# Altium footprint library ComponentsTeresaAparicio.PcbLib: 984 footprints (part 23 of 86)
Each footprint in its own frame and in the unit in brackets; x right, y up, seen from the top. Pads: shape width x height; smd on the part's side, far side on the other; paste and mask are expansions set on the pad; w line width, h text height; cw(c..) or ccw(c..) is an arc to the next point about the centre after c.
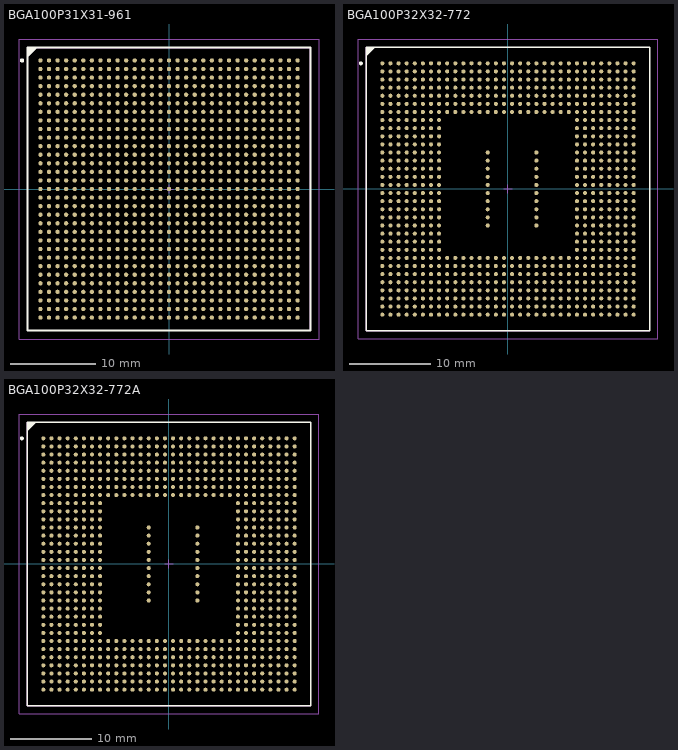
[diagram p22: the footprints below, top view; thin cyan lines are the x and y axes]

## BGA100P31X31-961 [mm] "BGA, 961-Leads, Body 33x33mm, Pitch 1mm"
height 3.5
pads (961):
  round 0.5 smd: A1(-15,15) A2(-14,15) A3(-13,15) A4(-12,15) A5(-11,15) A6(-10,15) A7(-9,15) A8(-8,15) A9(-7,15) A10(-6,15) A11(-5,15) A12(-4,15) A13(-3,15) A14(-2,15) A15(-1,15) A16(0,15) A17(1,15) A18(2,15) A19(3,15) A20(4,15) A21(5,15) A22(6,15) A23(7,15) A24(8,15) A25(9,15) A26(10,15) A27(11,15) A28(12,15) A29(13,15) A30(14,15) A31(15,15) AA1(-15,-5) AA2(-14,-5) AA3(-13,-5) AA4(-12,-5) AA5(-11,-5) AA6(-10,-5) AA7(-9,-5) AA8(-8,-5) AA9(-7,-5) AA10(-6,-5) AA11(-5,-5) AA12(-4,-5) AA13(-3,-5) AA14(-2,-5) AA15(-1,-5) AA16(0,-5) AA17(1,-5) AA18(2,-5) AA19(3,-5) AA20(4,-5) AA21(5,-5) AA22(6,-5) AA23(7,-5) AA24(8,-5) AA25(9,-5) AA26(10,-5) AA27(11,-5) AA28(12,-5) AA29(13,-5) AA30(14,-5) AA31(15,-5) AB1(-15,-6) AB2(-14,-6) AB3(-13,-6) AB4(-12,-6) AB5(-11,-6) AB6(-10,-6) AB7(-9,-6) AB8(-8,-6) AB9(-7,-6) AB10(-6,-6) AB11(-5,-6) AB12(-4,-6) AB13(-3,-6) AB14(-2,-6) AB15(-1,-6) AB16(0,-6) AB17(1,-6) AB18(2,-6) AB19(3,-6) AB20(4,-6) AB21(5,-6) AB22(6,-6) AB23(7,-6) AB24(8,-6) AB25(9,-6) AB26(10,-6) AB27(11,-6) AB28(12,-6) AB29(13,-6) AB30(14,-6) AB31(15,-6) AC1(-15,-7) AC2(-14,-7) AC3(-13,-7) AC4(-12,-7) AC5(-11,-7) AC6(-10,-7) AC7(-9,-7) AC8(-8,-7) AC9(-7,-7) AC10(-6,-7) AC11(-5,-7) AC12(-4,-7) AC13(-3,-7) AC14(-2,-7) AC15(-1,-7) AC16(0,-7) AC17(1,-7) AC18(2,-7) AC19(3,-7) AC20(4,-7) AC21(5,-7) AC22(6,-7) AC23(7,-7) AC24(8,-7) AC25(9,-7) AC26(10,-7) AC27(11,-7) AC28(12,-7) AC29(13,-7) AC30(14,-7) AC31(15,-7) AD1(-15,-8) AD2(-14,-8) AD3(-13,-8) AD4(-12,-8) AD5(-11,-8) AD6(-10,-8) AD7(-9,-8) AD8(-8,-8) AD9(-7,-8) AD10(-6,-8) AD11(-5,-8) AD12(-4,-8) AD13(-3,-8) AD14(-2,-8) AD15(-1,-8) AD16(0,-8) AD17(1,-8) AD18(2,-8) AD19(3,-8) AD20(4,-8) AD21(5,-8) AD22(6,-8) AD23(7,-8) AD24(8,-8) AD25(9,-8) AD26(10,-8) AD27(11,-8) AD28(12,-8) AD29(13,-8) AD30(14,-8) AD31(15,-8) AE1(-15,-9) AE2(-14,-9) AE3(-13,-9) AE4(-12,-9) AE5(-11,-9) AE6(-10,-9) AE7(-9,-9) AE8(-8,-9) AE9(-7,-9) AE10(-6,-9) AE11(-5,-9) AE12(-4,-9) AE13(-3,-9) AE14(-2,-9) AE15(-1,-9) AE16(0,-9) AE17(1,-9) AE18(2,-9) AE19(3,-9) AE20(4,-9) AE21(5,-9) AE22(6,-9) AE23(7,-9) AE24(8,-9) AE25(9,-9) AE26(10,-9) AE27(11,-9) AE28(12,-9) AE29(13,-9) AE30(14,-9) AE31(15,-9) AF1(-15,-10) AF2(-14,-10) AF3(-13,-10) AF4(-12,-10) AF5(-11,-10) AF6(-10,-10) AF7(-9,-10) AF8(-8,-10) AF9(-7,-10) AF10(-6,-10) AF11(-5,-10) AF12(-4,-10) AF13(-3,-10) AF14(-2,-10) AF15(-1,-10) AF16(0,-10) AF17(1,-10) AF18(2,-10) AF19(3,-10) AF20(4,-10) AF21(5,-10) AF22(6,-10) AF23(7,-10) AF24(8,-10) AF25(9,-10) AF26(10,-10) AF27(11,-10) AF28(12,-10) AF29(13,-10) AF30(14,-10) AF31(15,-10) AG1(-15,-11) AG2(-14,-11) AG3(-13,-11) AG4(-12,-11) AG5(-11,-11) AG6(-10,-11) AG7(-9,-11) AG8(-8,-11) AG9(-7,-11) AG10(-6,-11) AG11(-5,-11) AG12(-4,-11) AG13(-3,-11) AG14(-2,-11) AG15(-1,-11) AG16(0,-11) AG17(1,-11) AG18(2,-11) AG19(3,-11) AG20(4,-11) AG21(5,-11) AG22(6,-11) AG23(7,-11) AG24(8,-11) AG25(9,-11) AG26(10,-11) AG27(11,-11) AG28(12,-11) AG29(13,-11) AG30(14,-11) AG31(15,-11) AH1(-15,-12) AH2(-14,-12) AH3(-13,-12) AH4(-12,-12) AH5(-11,-12) AH6(-10,-12) AH7(-9,-12) AH8(-8,-12) AH9(-7,-12) AH10(-6,-12) AH11(-5,-12) AH12(-4,-12) AH13(-3,-12) AH14(-2,-12) AH15(-1,-12) AH16(0,-12) AH17(1,-12) AH18(2,-12) AH19(3,-12) AH20(4,-12) AH21(5,-12) AH22(6,-12) AH23(7,-12) AH24(8,-12) AH25(9,-12) AH26(10,-12) AH27(11,-12) AH28(12,-12) AH29(13,-12) AH30(14,-12) AH31(15,-12) AJ1(-15,-13) AJ2(-14,-13) AJ3(-13,-13) AJ4(-12,-13) AJ5(-11,-13) AJ6(-10,-13) AJ7(-9,-13) AJ8(-8,-13) AJ9(-7,-13) AJ10(-6,-13) AJ11(-5,-13) AJ12(-4,-13) AJ13(-3,-13) AJ14(-2,-13) AJ15(-1,-13) AJ16(0,-13) AJ17(1,-13) AJ18(2,-13) AJ19(3,-13) AJ20(4,-13) AJ21(5,-13) AJ22(6,-13) AJ23(7,-13) AJ24(8,-13) AJ25(9,-13) AJ26(10,-13) AJ27(11,-13) AJ28(12,-13) AJ29(13,-13) AJ30(14,-13) AJ31(15,-13) AK1(-15,-14) AK2(-14,-14) AK3(-13,-14) AK4(-12,-14) AK5(-11,-14) AK6(-10,-14) AK7(-9,-14) AK8(-8,-14) AK9(-7,-14) AK10(-6,-14) AK11(-5,-14) AK12(-4,-14) AK13(-3,-14) AK14(-2,-14) AK15(-1,-14) AK16(0,-14) AK17(1,-14) AK18(2,-14) AK19(3,-14) AK20(4,-14) AK21(5,-14) AK22(6,-14) AK23(7,-14) AK24(8,-14) AK25(9,-14) AK26(10,-14) AK27(11,-14) AK28(12,-14) AK29(13,-14) AK30(14,-14) AK31(15,-14) AL1(-15,-15) AL2(-14,-15) AL3(-13,-15) AL4(-12,-15) AL5(-11,-15) AL6(-10,-15) AL7(-9,-15) AL8(-8,-15) AL9(-7,-15) AL10(-6,-15) AL11(-5,-15) AL12(-4,-15) AL13(-3,-15) AL14(-2,-15) AL15(-1,-15) AL16(0,-15) AL17(1,-15) AL18(2,-15) AL19(3,-15) AL20(4,-15) AL21(5,-15) AL22(6,-15) AL23(7,-15) AL24(8,-15) AL25(9,-15) AL26(10,-15) AL27(11,-15) AL28(12,-15) AL29(13,-15) AL30(14,-15) AL31(15,-15) B1(-15,14) B2(-14,14) B3(-13,14) B4(-12,14) B5(-11,14) B6(-10,14) B7(-9,14) B8(-8,14) B9(-7,14) B10(-6,14) B11(-5,14) B12(-4,14) B13(-3,14) B14(-2,14) B15(-1,14) B16(0,14) B17(1,14) B18(2,14) B19(3,14) B20(4,14) B21(5,14) B22(6,14) B23(7,14) B24(8,14) B25(9,14) B26(10,14) B27(11,14) B28(12,14) B29(13,14) B30(14,14) B31(15,14) C1(-15,13) C2(-14,13) C3(-13,13) C4(-12,13) C5(-11,13) C6(-10,13) C7(-9,13) C8(-8,13) C9(-7,13) C10(-6,13) C11(-5,13) C12(-4,13) C13(-3,13) C14(-2,13) C15(-1,13) C16(0,13) C17(1,13) C18(2,13) C19(3,13) C20(4,13) C21(5,13) C22(6,13) C23(7,13) C24(8,13) C25(9,13) C26(10,13) C27(11,13) C28(12,13) C29(13,13) C30(14,13) C31(15,13) D1(-15,12) D2(-14,12) D3(-13,12) D4(-12,12) D5(-11,12) D6(-10,12) D7(-9,12) D8(-8,12) D9(-7,12) D10(-6,12) D11(-5,12) D12(-4,12) D13(-3,12) D14(-2,12) D15(-1,12) D16(0,12) D17(1,12) D18(2,12) D19(3,12) D20(4,12) D21(5,12) D22(6,12) D23(7,12) D24(8,12) D25(9,12) D26(10,12) D27(11,12) D28(12,12) D29(13,12) D30(14,12) D31(15,12) E1(-15,11) E2(-14,11) E3(-13,11) E4(-12,11) E5(-11,11) E6(-10,11) E7(-9,11) E8(-8,11) E9(-7,11) E10(-6,11) E11(-5,11) E12(-4,11) E13(-3,11) E14(-2,11) E15(-1,11) E16(0,11) E17(1,11) E18(2,11) E19(3,11) E20(4,11) E21(5,11) E22(6,11) E23(7,11) E24(8,11) E25(9,11) E26(10,11) E27(11,11) E28(12,11) E29(13,11) E30(14,11) E31(15,11) F1(-15,10) F2(-14,10) F3(-13,10) F4(-12,10) F5(-11,10) F6(-10,10) F7(-9,10) F8(-8,10) F9(-7,10) F10(-6,10) F11(-5,10) F12(-4,10) F13(-3,10) F14(-2,10) F15(-1,10) F16(0,10) F17(1,10) F18(2,10) F19(3,10) F20(4,10) F21(5,10) F22(6,10) F23(7,10) F24(8,10) F25(9,10) F26(10,10) F27(11,10) F28(12,10) F29(13,10) F30(14,10) F31(15,10) G1(-15,9) G2(-14,9) G3(-13,9) G4(-12,9) G5(-11,9) G6(-10,9) G7(-9,9) G8(-8,9) G9(-7,9) G10(-6,9) G11(-5,9) G12(-4,9) G13(-3,9) G14(-2,9) G15(-1,9) G16(0,9) G17(1,9) G18(2,9) G19(3,9) G20(4,9) G21(5,9) G22(6,9) G23(7,9) G24(8,9) G25(9,9) G26(10,9) G27(11,9) G28(12,9) G29(13,9) G30(14,9) G31(15,9) H1(-15,8) H2(-14,8) H3(-13,8) H4(-12,8) H5(-11,8) H6(-10,8) H7(-9,8) H8(-8,8) H9(-7,8) H10(-6,8) H11(-5,8) H12(-4,8) H13(-3,8) H14(-2,8) H15(-1,8) H16(0,8) H17(1,8) H18(2,8) H19(3,8) H20(4,8) H21(5,8) H22(6,8) H23(7,8) H24(8,8) H25(9,8) H26(10,8) H27(11,8) H28(12,8) H29(13,8) H30(14,8) H31(15,8) J1(-15,7) J2(-14,7) J3(-13,7) J4(-12,7) J5(-11,7) J6(-10,7) J7(-9,7) J8(-8,7) J9(-7,7) J10(-6,7) J11(-5,7) J12(-4,7) J13(-3,7) J14(-2,7) J15(-1,7) J16(0,7) J17(1,7) J18(2,7) J19(3,7) J20(4,7) J21(5,7) J22(6,7) J23(7,7) J24(8,7) J25(9,7) J26(10,7) J27(11,7) J28(12,7) J29(13,7) J30(14,7) J31(15,7) K1(-15,6) K2(-14,6) K3(-13,6) K4(-12,6) K5(-11,6) K6(-10,6) K7(-9,6) K8(-8,6) K9(-7,6) K10(-6,6) K11(-5,6) K12(-4,6) K13(-3,6) K14(-2,6) K15(-1,6) K16(0,6) K17(1,6) K18(2,6) K19(3,6) K20(4,6) K21(5,6) K22(6,6) K23(7,6) K24(8,6) K25(9,6) K26(10,6) K27(11,6) K28(12,6) K29(13,6) K30(14,6) K31(15,6) L1(-15,5) L2(-14,5) L3(-13,5) L4(-12,5) L5(-11,5) L6(-10,5) L7(-9,5) L8(-8,5) L9(-7,5) L10(-6,5) L11(-5,5) L12(-4,5) L13(-3,5) L14(-2,5) L15(-1,5) L16(0,5) L17(1,5) L18(2,5) L19(3,5) L20(4,5) L21(5,5) L22(6,5) L23(7,5) L24(8,5) L25(9,5) L26(10,5) L27(11,5) L28(12,5) L29(13,5) L30(14,5) L31(15,5) M1(-15,4) M2(-14,4) M3(-13,4) M4(-12,4) M5(-11,4) M6(-10,4) M7(-9,4) M8(-8,4) M9(-7,4) M10(-6,4) M11(-5,4) M12(-4,4) M13(-3,4) M14(-2,4) M15(-1,4) M16(0,4) M17(1,4) M18(2,4) M19(3,4) M20(4,4) M21(5,4) M22(6,4) M23(7,4) M24(8,4) M25(9,4) M26(10,4) M27(11,4) M28(12,4) M29(13,4) M30(14,4) M31(15,4) N1(-15,3) N2(-14,3) N3(-13,3) N4(-12,3) N5(-11,3) N6(-10,3) N7(-9,3) N8(-8,3) N9(-7,3) N10(-6,3) N11(-5,3) N12(-4,3) N13(-3,3) N14(-2,3) N15(-1,3) N16(0,3) N17(1,3) N18(2,3) N19(3,3) N20(4,3) N21(5,3) N22(6,3) N23(7,3) N24(8,3) N25(9,3) N26(10,3) N27(11,3) N28(12,3) N29(13,3) N30(14,3) N31(15,3) P1(-15,2) P2(-14,2) P3(-13,2) P4(-12,2) P5(-11,2) P6(-10,2) P7(-9,2) P8(-8,2) P9(-7,2) P10(-6,2) P11(-5,2) P12(-4,2) P13(-3,2) P14(-2,2) P15(-1,2) P16(0,2) P17(1,2) P18(2,2) P19(3,2) P20(4,2) P21(5,2) P22(6,2) P23(7,2) P24(8,2) P25(9,2) P26(10,2) P27(11,2) P28(12,2) P29(13,2) P30(14,2) P31(15,2) R1(-15,1) R2(-14,1) R3(-13,1) R4(-12,1) R5(-11,1) R6(-10,1) R7(-9,1) R8(-8,1) R9(-7,1) R10(-6,1) R11(-5,1) R12(-4,1) R13(-3,1) R14(-2,1) R15(-1,1) R16(0,1) R17(1,1) R18(2,1) R19(3,1) R20(4,1) R21(5,1) R22(6,1) R23(7,1) R24(8,1) R25(9,1) R26(10,1) R27(11,1) R28(12,1) R29(13,1) R30(14,1) R31(15,1) T1(-15,0) T2(-14,0) T3(-13,0) T4(-12,0) T5(-11,0) T6(-10,0) T7(-9,0) T8(-8,0) T9(-7,0) T10(-6,0) T11(-5,0) T12(-4,0) T13(-3,0) T14(-2,0) T15(-1,0) T16(0,0) T17(1,0) T18(2,0) T19(3,0) T20(4,0) T21(5,0) T22(6,0) T23(7,0) T24(8,0) T25(9,0) T26(10,0) T27(11,0) T28(12,0) T29(13,0) T30(14,0) T31(15,0) U1(-15,-1) U2(-14,-1) U3(-13,-1) U4(-12,-1) U5(-11,-1) U6(-10,-1) U7(-9,-1) U8(-8,-1) U9(-7,-1) U10(-6,-1) U11(-5,-1) U12(-4,-1) U13(-3,-1) U14(-2,-1) U15(-1,-1) U16(0,-1) U17(1,-1) U18(2,-1) U19(3,-1) U20(4,-1) U21(5,-1) U22(6,-1) U23(7,-1) U24(8,-1) U25(9,-1) U26(10,-1) U27(11,-1) U28(12,-1) U29(13,-1) U30(14,-1) U31(15,-1) V1(-15,-2) V2(-14,-2) V3(-13,-2) V4(-12,-2) V5(-11,-2) V6(-10,-2) V7(-9,-2) V8(-8,-2) V9(-7,-2) V10(-6,-2) V11(-5,-2) V12(-4,-2) V13(-3,-2) V14(-2,-2) V15(-1,-2) V16(0,-2) V17(1,-2) V18(2,-2) V19(3,-2) V20(4,-2) V21(5,-2) V22(6,-2) V23(7,-2) V24(8,-2) V25(9,-2) V26(10,-2) V27(11,-2) V28(12,-2) V29(13,-2) V30(14,-2) V31(15,-2) W1(-15,-3) W2(-14,-3) W3(-13,-3) W4(-12,-3) W5(-11,-3) W6(-10,-3) W7(-9,-3) W8(-8,-3) W9(-7,-3) W10(-6,-3) W11(-5,-3) W12(-4,-3) W13(-3,-3) W14(-2,-3) W15(-1,-3) W16(0,-3) W17(1,-3) W18(2,-3) W19(3,-3) W20(4,-3) W21(5,-3) W22(6,-3) W23(7,-3) W24(8,-3) W25(9,-3) W26(10,-3) W27(11,-3) W28(12,-3) W29(13,-3) W30(14,-3) W31(15,-3) Y1(-15,-4) Y2(-14,-4) Y3(-13,-4) Y4(-12,-4) Y5(-11,-4) Y6(-10,-4) Y7(-9,-4) Y8(-8,-4) Y9(-7,-4) Y10(-6,-4) Y11(-5,-4) Y12(-4,-4) Y13(-3,-4) Y14(-2,-4) Y15(-1,-4) Y16(0,-4) Y17(1,-4) Y18(2,-4) Y19(3,-4) Y20(4,-4) Y21(5,-4) Y22(6,-4) Y23(7,-4) Y24(8,-4) Y25(9,-4) Y26(10,-4) Y27(11,-4) Y28(12,-4) Y29(13,-4) Y30(14,-4) Y31(15,-4)
Top Overlay:
  circle w0.25: c-17.15,15 r0.125
  region: -15.5,16.5 -16.5,15.5 -16.5,16.5
  lines w0.2: -16.5,15.5 -15.5,16.5 ; -16.5,-16.5 -16.5,16.5 16.5,16.5 16.5,-16.5 -16.5,-16.5
Mechanical 13:
  lines w0.1: -16.5,-16.5 -16.5,16.5 16.5,16.5 16.5,-16.5 -16.5,-16.5
Mechanical 15:
  lines w0.1: -0.5,0 0.5,0 ; 0,-0.5 0,0.5 ; -17.5,-17.5 -17.5,17.5 17.5,17.5 17.5,-17.5 -17.5,-17.5
3D body: height 0, standoff 0, extent -16.5,-16.5 16.5,16.5

## BGA100P32X32-772 [mm] "772-Ball Ball Grid Array 1 mm Pitch"
height 3.6
pads (772):
  round 0.5 smd: A1(-15.5,15.5) A2(-14.5,15.5) A3(-13.5,15.5) A4(-12.5,15.5) A5(-11.5,15.5) A6(-10.5,15.5) A7(-9.5,15.5) A8(-8.5,15.5) A9(-7.5,15.5) A10(-6.5,15.5) A11(-5.5,15.5) A12(-4.5,15.5) A13(-3.5,15.5) A14(-2.5,15.5) A15(-1.5,15.5) A16(-0.5,15.5) A17(0.5,15.5) A18(1.5,15.5) A19(2.5,15.5) A20(3.5,15.5) A21(4.5,15.5) A22(5.5,15.5) A23(6.5,15.5) A24(7.5,15.5) A25(8.5,15.5) A26(9.5,15.5) A27(10.5,15.5) A28(11.5,15.5) A29(12.5,15.5) A30(13.5,15.5) A31(14.5,15.5) A32(15.5,15.5) AA1(-15.5,-4.5) AA2(-14.5,-4.5) AA3(-13.5,-4.5) AA4(-12.5,-4.5) AA5(-11.5,-4.5) AA6(-10.5,-4.5) AA7(-9.5,-4.5) AA8(-8.5,-4.5) AA14(-2.5,-4.5) AA20(3.5,-4.5) AA25(8.5,-4.5) AA26(9.5,-4.5) AA27(10.5,-4.5) AA28(11.5,-4.5) AA29(12.5,-4.5) AA30(13.5,-4.5) AA31(14.5,-4.5) AA32(15.5,-4.5) AB1(-15.5,-5.5) AB2(-14.5,-5.5) AB3(-13.5,-5.5) AB4(-12.5,-5.5) AB5(-11.5,-5.5) AB6(-10.5,-5.5) AB7(-9.5,-5.5) AB8(-8.5,-5.5) AB25(8.5,-5.5) AB26(9.5,-5.5) AB27(10.5,-5.5) AB28(11.5,-5.5) AB29(12.5,-5.5) AB30(13.5,-5.5) AB31(14.5,-5.5) AB32(15.5,-5.5) AC1(-15.5,-6.5) AC2(-14.5,-6.5) AC3(-13.5,-6.5) AC4(-12.5,-6.5) AC5(-11.5,-6.5) AC6(-10.5,-6.5) AC7(-9.5,-6.5) AC8(-8.5,-6.5) AC25(8.5,-6.5) AC26(9.5,-6.5) AC27(10.5,-6.5) AC28(11.5,-6.5) AC29(12.5,-6.5) AC30(13.5,-6.5) AC31(14.5,-6.5) AC32(15.5,-6.5) AD1(-15.5,-7.5) AD2(-14.5,-7.5) AD3(-13.5,-7.5) AD4(-12.5,-7.5) AD5(-11.5,-7.5) AD6(-10.5,-7.5) AD7(-9.5,-7.5) AD8(-8.5,-7.5) AD25(8.5,-7.5) AD26(9.5,-7.5) AD27(10.5,-7.5) AD28(11.5,-7.5) AD29(12.5,-7.5) AD30(13.5,-7.5) AD31(14.5,-7.5) AD32(15.5,-7.5) AE1(-15.5,-8.5) AE2(-14.5,-8.5) AE3(-13.5,-8.5) AE4(-12.5,-8.5) AE5(-11.5,-8.5) AE6(-10.5,-8.5) AE7(-9.5,-8.5) AE8(-8.5,-8.5) AE9(-7.5,-8.5) AE10(-6.5,-8.5) AE11(-5.5,-8.5) AE12(-4.5,-8.5) AE13(-3.5,-8.5) AE14(-2.5,-8.5) AE15(-1.5,-8.5) AE16(-0.5,-8.5) AE17(0.5,-8.5) AE18(1.5,-8.5) AE19(2.5,-8.5) AE20(3.5,-8.5) AE21(4.5,-8.5) AE22(5.5,-8.5) AE23(6.5,-8.5) AE24(7.5,-8.5) AE25(8.5,-8.5) AE26(9.5,-8.5) AE27(10.5,-8.5) AE28(11.5,-8.5) AE29(12.5,-8.5) AE30(13.5,-8.5) AE31(14.5,-8.5) AE32(15.5,-8.5) AF1(-15.5,-9.5) AF2(-14.5,-9.5) AF3(-13.5,-9.5) AF4(-12.5,-9.5) AF5(-11.5,-9.5) AF6(-10.5,-9.5) AF7(-9.5,-9.5) AF8(-8.5,-9.5) AF9(-7.5,-9.5) AF10(-6.5,-9.5) AF11(-5.5,-9.5) AF12(-4.5,-9.5) AF13(-3.5,-9.5) AF14(-2.5,-9.5) AF15(-1.5,-9.5) AF16(-0.5,-9.5) AF17(0.5,-9.5) AF18(1.5,-9.5) AF19(2.5,-9.5) AF20(3.5,-9.5) AF21(4.5,-9.5) AF22(5.5,-9.5) AF23(6.5,-9.5) AF24(7.5,-9.5) AF25(8.5,-9.5) AF26(9.5,-9.5) AF27(10.5,-9.5) AF28(11.5,-9.5) AF29(12.5,-9.5) AF30(13.5,-9.5) AF31(14.5,-9.5) AF32(15.5,-9.5) AG1(-15.5,-10.5) AG2(-14.5,-10.5) AG3(-13.5,-10.5) AG4(-12.5,-10.5) AG5(-11.5,-10.5) AG6(-10.5,-10.5) AG7(-9.5,-10.5) AG8(-8.5,-10.5) AG9(-7.5,-10.5) AG10(-6.5,-10.5) AG11(-5.5,-10.5) AG12(-4.5,-10.5) AG13(-3.5,-10.5) AG14(-2.5,-10.5) AG15(-1.5,-10.5) AG16(-0.5,-10.5) AG17(0.5,-10.5) AG18(1.5,-10.5) AG19(2.5,-10.5) AG20(3.5,-10.5) AG21(4.5,-10.5) AG22(5.5,-10.5) AG23(6.5,-10.5) AG24(7.5,-10.5) AG25(8.5,-10.5) AG26(9.5,-10.5) AG27(10.5,-10.5) AG28(11.5,-10.5) AG29(12.5,-10.5) AG30(13.5,-10.5) AG31(14.5,-10.5) AG32(15.5,-10.5) AH1(-15.5,-11.5) AH2(-14.5,-11.5) AH3(-13.5,-11.5) AH4(-12.5,-11.5) AH5(-11.5,-11.5) AH6(-10.5,-11.5) AH7(-9.5,-11.5) AH8(-8.5,-11.5) AH9(-7.5,-11.5) AH10(-6.5,-11.5) AH11(-5.5,-11.5) AH12(-4.5,-11.5) AH13(-3.5,-11.5) AH14(-2.5,-11.5) AH15(-1.5,-11.5) AH16(-0.5,-11.5) AH17(0.5,-11.5) AH18(1.5,-11.5) AH19(2.5,-11.5) AH20(3.5,-11.5) AH21(4.5,-11.5) AH22(5.5,-11.5) AH23(6.5,-11.5) AH24(7.5,-11.5) AH25(8.5,-11.5) AH26(9.5,-11.5) AH27(10.5,-11.5) AH28(11.5,-11.5) AH29(12.5,-11.5) AH30(13.5,-11.5) AH31(14.5,-11.5) AH32(15.5,-11.5) AJ1(-15.5,-12.5) AJ2(-14.5,-12.5) AJ3(-13.5,-12.5) AJ4(-12.5,-12.5) AJ5(-11.5,-12.5) AJ6(-10.5,-12.5) AJ7(-9.5,-12.5) AJ8(-8.5,-12.5) AJ9(-7.5,-12.5) AJ10(-6.5,-12.5) AJ11(-5.5,-12.5) AJ12(-4.5,-12.5) AJ13(-3.5,-12.5) AJ14(-2.5,-12.5) AJ15(-1.5,-12.5) AJ16(-0.5,-12.5) AJ17(0.5,-12.5) AJ18(1.5,-12.5) AJ19(2.5,-12.5) AJ20(3.5,-12.5) AJ21(4.5,-12.5) AJ22(5.5,-12.5) AJ23(6.5,-12.5) AJ24(7.5,-12.5) AJ25(8.5,-12.5) AJ26(9.5,-12.5) AJ27(10.5,-12.5) AJ28(11.5,-12.5) AJ29(12.5,-12.5) AJ30(13.5,-12.5) AJ31(14.5,-12.5) AJ32(15.5,-12.5) AK1(-15.5,-13.5) AK2(-14.5,-13.5) AK3(-13.5,-13.5) AK4(-12.5,-13.5) AK5(-11.5,-13.5) AK6(-10.5,-13.5) AK7(-9.5,-13.5) AK8(-8.5,-13.5) AK9(-7.5,-13.5) AK10(-6.5,-13.5) AK11(-5.5,-13.5) AK12(-4.5,-13.5) AK13(-3.5,-13.5) AK14(-2.5,-13.5) AK15(-1.5,-13.5) AK16(-0.5,-13.5) AK17(0.5,-13.5) AK18(1.5,-13.5) AK19(2.5,-13.5) AK20(3.5,-13.5) AK21(4.5,-13.5) AK22(5.5,-13.5) AK23(6.5,-13.5) AK24(7.5,-13.5) AK25(8.5,-13.5) AK26(9.5,-13.5) AK27(10.5,-13.5) AK28(11.5,-13.5) AK29(12.5,-13.5) AK30(13.5,-13.5) AK31(14.5,-13.5) AK32(15.5,-13.5) AL1(-15.5,-14.5) AL2(-14.5,-14.5) AL3(-13.5,-14.5) AL4(-12.5,-14.5) AL5(-11.5,-14.5) AL6(-10.5,-14.5) AL7(-9.5,-14.5) AL8(-8.5,-14.5) AL9(-7.5,-14.5) AL10(-6.5,-14.5) AL11(-5.5,-14.5) AL12(-4.5,-14.5) AL13(-3.5,-14.5) AL14(-2.5,-14.5) AL15(-1.5,-14.5) AL16(-0.5,-14.5) AL17(0.5,-14.5) AL18(1.5,-14.5) AL19(2.5,-14.5) AL20(3.5,-14.5) AL21(4.5,-14.5) AL22(5.5,-14.5) AL23(6.5,-14.5) AL24(7.5,-14.5) AL25(8.5,-14.5) AL26(9.5,-14.5) AL27(10.5,-14.5) AL28(11.5,-14.5) AL29(12.5,-14.5) AL30(13.5,-14.5) AL31(14.5,-14.5) AL32(15.5,-14.5) AM1(-15.5,-15.5) AM2(-14.5,-15.5) AM3(-13.5,-15.5) AM4(-12.5,-15.5) AM5(-11.5,-15.5) AM6(-10.5,-15.5) AM7(-9.5,-15.5) AM8(-8.5,-15.5) AM9(-7.5,-15.5) AM10(-6.5,-15.5) AM11(-5.5,-15.5) AM12(-4.5,-15.5) AM13(-3.5,-15.5) AM14(-2.5,-15.5) AM15(-1.5,-15.5) AM16(-0.5,-15.5) AM17(0.5,-15.5) AM18(1.5,-15.5) AM19(2.5,-15.5) AM20(3.5,-15.5) AM21(4.5,-15.5) AM22(5.5,-15.5) AM23(6.5,-15.5) AM24(7.5,-15.5) AM25(8.5,-15.5) AM26(9.5,-15.5) AM27(10.5,-15.5) AM28(11.5,-15.5) AM29(12.5,-15.5) AM30(13.5,-15.5) AM31(14.5,-15.5) AM32(15.5,-15.5) B1(-15.5,14.5) B2(-14.5,14.5) B3(-13.5,14.5) B4(-12.5,14.5) B5(-11.5,14.5) B6(-10.5,14.5) B7(-9.5,14.5) B8(-8.5,14.5) B9(-7.5,14.5) B10(-6.5,14.5) B11(-5.5,14.5) B12(-4.5,14.5) B13(-3.5,14.5) B14(-2.5,14.5) B15(-1.5,14.5) B16(-0.5,14.5) B17(0.5,14.5) B18(1.5,14.5) B19(2.5,14.5) B20(3.5,14.5) B21(4.5,14.5) B22(5.5,14.5) B23(6.5,14.5) B24(7.5,14.5) B25(8.5,14.5) B26(9.5,14.5) B27(10.5,14.5) B28(11.5,14.5) B29(12.5,14.5) B30(13.5,14.5) B31(14.5,14.5) B32(15.5,14.5) C1(-15.5,13.5) C2(-14.5,13.5) C3(-13.5,13.5) C4(-12.5,13.5) C5(-11.5,13.5) C6(-10.5,13.5) C7(-9.5,13.5) C8(-8.5,13.5) C9(-7.5,13.5) C10(-6.5,13.5) C11(-5.5,13.5) C12(-4.5,13.5) C13(-3.5,13.5) C14(-2.5,13.5) C15(-1.5,13.5) C16(-0.5,13.5) C17(0.5,13.5) C18(1.5,13.5) C19(2.5,13.5) C20(3.5,13.5) C21(4.5,13.5) C22(5.5,13.5) C23(6.5,13.5) C24(7.5,13.5) C25(8.5,13.5) C26(9.5,13.5) C27(10.5,13.5) C28(11.5,13.5) C29(12.5,13.5) C30(13.5,13.5) C31(14.5,13.5) C32(15.5,13.5) D1(-15.5,12.5) D2(-14.5,12.5) D3(-13.5,12.5) D4(-12.5,12.5) D5(-11.5,12.5) D6(-10.5,12.5) D7(-9.5,12.5) D8(-8.5,12.5) D9(-7.5,12.5) D10(-6.5,12.5) D11(-5.5,12.5) D12(-4.5,12.5) D13(-3.5,12.5) D14(-2.5,12.5) D15(-1.5,12.5) D16(-0.5,12.5) D17(0.5,12.5) D18(1.5,12.5) D19(2.5,12.5) D20(3.5,12.5) D21(4.5,12.5) D22(5.5,12.5) D23(6.5,12.5) D24(7.5,12.5) D25(8.5,12.5) D26(9.5,12.5) D27(10.5,12.5) D28(11.5,12.5) D29(12.5,12.5) D30(13.5,12.5) D31(14.5,12.5) D32(15.5,12.5) E1(-15.5,11.5) E2(-14.5,11.5) E3(-13.5,11.5) E4(-12.5,11.5) E5(-11.5,11.5) E6(-10.5,11.5) E7(-9.5,11.5) E8(-8.5,11.5) E9(-7.5,11.5) E10(-6.5,11.5) E11(-5.5,11.5) E12(-4.5,11.5) E13(-3.5,11.5) E14(-2.5,11.5) E15(-1.5,11.5) E16(-0.5,11.5) E17(0.5,11.5) E18(1.5,11.5) E19(2.5,11.5) E20(3.5,11.5) E21(4.5,11.5) E22(5.5,11.5) E23(6.5,11.5) E24(7.5,11.5) E25(8.5,11.5) E26(9.5,11.5) E27(10.5,11.5) E28(11.5,11.5) E29(12.5,11.5) E30(13.5,11.5) E31(14.5,11.5) E32(15.5,11.5) F1(-15.5,10.5) F2(-14.5,10.5) F3(-13.5,10.5) F4(-12.5,10.5) F5(-11.5,10.5) F6(-10.5,10.5) F7(-9.5,10.5) F8(-8.5,10.5) F9(-7.5,10.5) F10(-6.5,10.5) F11(-5.5,10.5) F12(-4.5,10.5) F13(-3.5,10.5) F14(-2.5,10.5) F15(-1.5,10.5) F16(-0.5,10.5) F17(0.5,10.5) F18(1.5,10.5) F19(2.5,10.5) F20(3.5,10.5) F21(4.5,10.5) F22(5.5,10.5) F23(6.5,10.5) F24(7.5,10.5) F25(8.5,10.5) F26(9.5,10.5) F27(10.5,10.5) F28(11.5,10.5) F29(12.5,10.5) F30(13.5,10.5) F31(14.5,10.5) F32(15.5,10.5) G1(-15.5,9.5) G2(-14.5,9.5) G3(-13.5,9.5) G4(-12.5,9.5) G5(-11.5,9.5) G6(-10.5,9.5) G7(-9.5,9.5) G8(-8.5,9.5) G9(-7.5,9.5) G10(-6.5,9.5) G11(-5.5,9.5) G12(-4.5,9.5) G13(-3.5,9.5) G14(-2.5,9.5) G15(-1.5,9.5) G16(-0.5,9.5) G17(0.5,9.5) G18(1.5,9.5) G19(2.5,9.5) G20(3.5,9.5) G21(4.5,9.5) G22(5.5,9.5) G23(6.5,9.5) G24(7.5,9.5) G25(8.5,9.5) G26(9.5,9.5) G27(10.5,9.5) G28(11.5,9.5) G29(12.5,9.5) G30(13.5,9.5) G31(14.5,9.5) G32(15.5,9.5) H1(-15.5,8.5) H2(-14.5,8.5) H3(-13.5,8.5) H4(-12.5,8.5) H5(-11.5,8.5) H6(-10.5,8.5) H7(-9.5,8.5) H8(-8.5,8.5) H25(8.5,8.5) H26(9.5,8.5) H27(10.5,8.5) H28(11.5,8.5) H29(12.5,8.5) H30(13.5,8.5) H31(14.5,8.5) H32(15.5,8.5) J1(-15.5,7.5) J2(-14.5,7.5) J3(-13.5,7.5) J4(-12.5,7.5) J5(-11.5,7.5) J6(-10.5,7.5) J7(-9.5,7.5) J8(-8.5,7.5) J25(8.5,7.5) J26(9.5,7.5) J27(10.5,7.5) J28(11.5,7.5) J29(12.5,7.5) J30(13.5,7.5) J31(14.5,7.5) J32(15.5,7.5) K1(-15.5,6.5) K2(-14.5,6.5) K3(-13.5,6.5) K4(-12.5,6.5) K5(-11.5,6.5) K6(-10.5,6.5) K7(-9.5,6.5) K8(-8.5,6.5) K25(8.5,6.5) K26(9.5,6.5) K27(10.5,6.5) K28(11.5,6.5) K29(12.5,6.5) K30(13.5,6.5) K31(14.5,6.5) K32(15.5,6.5) L1(-15.5,5.5) L2(-14.5,5.5) L3(-13.5,5.5) L4(-12.5,5.5) L5(-11.5,5.5) L6(-10.5,5.5) L7(-9.5,5.5) L8(-8.5,5.5) L25(8.5,5.5) L26(9.5,5.5) L27(10.5,5.5) L28(11.5,5.5) L29(12.5,5.5) L30(13.5,5.5) L31(14.5,5.5) L32(15.5,5.5) M1(-15.5,4.5) M2(-14.5,4.5) M3(-13.5,4.5) M4(-12.5,4.5) M5(-11.5,4.5) M6(-10.5,4.5) M7(-9.5,4.5) M8(-8.5,4.5) M14(-2.5,4.5) M20(3.5,4.5) M25(8.5,4.5) M26(9.5,4.5) M27(10.5,4.5) M28(11.5,4.5) M29(12.5,4.5) M30(13.5,4.5) M31(14.5,4.5) M32(15.5,4.5) N1(-15.5,3.5) N2(-14.5,3.5) N3(-13.5,3.5) N4(-12.5,3.5) N5(-11.5,3.5) N6(-10.5,3.5) N7(-9.5,3.5) N8(-8.5,3.5) N14(-2.5,3.5) N20(3.5,3.5) N25(8.5,3.5) N26(9.5,3.5) N27(10.5,3.5) N28(11.5,3.5) N29(12.5,3.5) N30(13.5,3.5) N31(14.5,3.5) N32(15.5,3.5) P1(-15.5,2.5) P2(-14.5,2.5) P3(-13.5,2.5) P4(-12.5,2.5) P5(-11.5,2.5) P6(-10.5,2.5) P7(-9.5,2.5) P8(-8.5,2.5) P14(-2.5,2.5) P20(3.5,2.5) P25(8.5,2.5) P26(9.5,2.5) P27(10.5,2.5) P28(11.5,2.5) P29(12.5,2.5) P30(13.5,2.5) P31(14.5,2.5) P32(15.5,2.5) R1(-15.5,1.5) R2(-14.5,1.5) R3(-13.5,1.5) R4(-12.5,1.5) R5(-11.5,1.5) R6(-10.5,1.5) R7(-9.5,1.5) R8(-8.5,1.5) R14(-2.5,1.5) R20(3.5,1.5) R25(8.5,1.5) R26(9.5,1.5) R27(10.5,1.5) R28(11.5,1.5) R29(12.5,1.5) R30(13.5,1.5) R31(14.5,1.5) R32(15.5,1.5) T1(-15.5,0.5) T2(-14.5,0.5) T3(-13.5,0.5) T4(-12.5,0.5) T5(-11.5,0.5) T6(-10.5,0.5) T7(-9.5,0.5) T8(-8.5,0.5) T14(-2.5,0.5) T20(3.5,0.5) T25(8.5,0.5) T26(9.5,0.5) T27(10.5,0.5) T28(11.5,0.5) T29(12.5,0.5) T30(13.5,0.5) T31(14.5,0.5) T32(15.5,0.5) U1(-15.5,-0.5) U2(-14.5,-0.5) U3(-13.5,-0.5) U4(-12.5,-0.5) U5(-11.5,-0.5) U6(-10.5,-0.5) U7(-9.5,-0.5) U8(-8.5,-0.5) U14(-2.5,-0.5) U20(3.5,-0.5) U25(8.5,-0.5) U26(9.5,-0.5) U27(10.5,-0.5) U28(11.5,-0.5) U29(12.5,-0.5) U30(13.5,-0.5) U31(14.5,-0.5) U32(15.5,-0.5) V1(-15.5,-1.5) V2(-14.5,-1.5) V3(-13.5,-1.5) V4(-12.5,-1.5) V5(-11.5,-1.5) V6(-10.5,-1.5) V7(-9.5,-1.5) V8(-8.5,-1.5) V14(-2.5,-1.5) V20(3.5,-1.5) V25(8.5,-1.5) V26(9.5,-1.5) V27(10.5,-1.5) V28(11.5,-1.5) V29(12.5,-1.5) V30(13.5,-1.5) V31(14.5,-1.5) V32(15.5,-1.5) W1(-15.5,-2.5) W2(-14.5,-2.5) W3(-13.5,-2.5) W4(-12.5,-2.5) W5(-11.5,-2.5) W6(-10.5,-2.5) W7(-9.5,-2.5) W8(-8.5,-2.5) W14(-2.5,-2.5) W20(3.5,-2.5) W25(8.5,-2.5) W26(9.5,-2.5) W27(10.5,-2.5) W28(11.5,-2.5) W29(12.5,-2.5) W30(13.5,-2.5) W31(14.5,-2.5) W32(15.5,-2.5) Y1(-15.5,-3.5) Y2(-14.5,-3.5) Y3(-13.5,-3.5) Y4(-12.5,-3.5) Y5(-11.5,-3.5) Y6(-10.5,-3.5) Y7(-9.5,-3.5) Y8(-8.5,-3.5) Y14(-2.5,-3.5) Y20(3.5,-3.5) Y25(8.5,-3.5) Y26(9.5,-3.5) Y27(10.5,-3.5) Y28(11.5,-3.5) Y29(12.5,-3.5) Y30(13.5,-3.5) Y31(14.5,-3.5) Y32(15.5,-3.5)
Top Overlay:
  circle w0.25: c-18.15,15.5 r0.125
  region: -16.5,17.5 -17.5,16.5 -17.5,17.5
  lines w0.2: -17.5,16.5 -16.5,17.5 ; -17.5,-17.5 17.5,-17.5 17.5,17.5 -17.5,17.5 -17.5,-17.5
Mechanical 13:
  lines w0.1: -17.5,-17.5 17.5,-17.5 17.5,17.5 -17.5,17.5 -17.5,-17.5
Mechanical 15:
  lines w0.1: -0.5,0 0.5,0 ; 0,-0.5 0,0.5 ; -18.5,-18.5 18.5,-18.5 18.5,18.5 -18.5,18.5 -18.5,-18.5
3D body: height 0, standoff 0, extent -17.5,-17.5 17.5,17.5

## BGA100P32X32-772A [mm] "772-Ball Ball Grid Array 1 mm Pitch"
height 3.48
pads (772):
  round 0.5 smd: A1(-15.5,15.5) A2(-14.5,15.5) A3(-13.5,15.5) A4(-12.5,15.5) A5(-11.5,15.5) A6(-10.5,15.5) A7(-9.5,15.5) A8(-8.5,15.5) A9(-7.5,15.5) A10(-6.5,15.5) A11(-5.5,15.5) A12(-4.5,15.5) A13(-3.5,15.5) A14(-2.5,15.5) A15(-1.5,15.5) A16(-0.5,15.5) A17(0.5,15.5) A18(1.5,15.5) A19(2.5,15.5) A20(3.5,15.5) A21(4.5,15.5) A22(5.5,15.5) A23(6.5,15.5) A24(7.5,15.5) A25(8.5,15.5) A26(9.5,15.5) A27(10.5,15.5) A28(11.5,15.5) A29(12.5,15.5) A30(13.5,15.5) A31(14.5,15.5) A32(15.5,15.5) AA1(-15.5,-4.5) AA2(-14.5,-4.5) AA3(-13.5,-4.5) AA4(-12.5,-4.5) AA5(-11.5,-4.5) AA6(-10.5,-4.5) AA7(-9.5,-4.5) AA8(-8.5,-4.5) AA14(-2.5,-4.5) AA20(3.5,-4.5) AA25(8.5,-4.5) AA26(9.5,-4.5) AA27(10.5,-4.5) AA28(11.5,-4.5) AA29(12.5,-4.5) AA30(13.5,-4.5) AA31(14.5,-4.5) AA32(15.5,-4.5) AB1(-15.5,-5.5) AB2(-14.5,-5.5) AB3(-13.5,-5.5) AB4(-12.5,-5.5) AB5(-11.5,-5.5) AB6(-10.5,-5.5) AB7(-9.5,-5.5) AB8(-8.5,-5.5) AB25(8.5,-5.5) AB26(9.5,-5.5) AB27(10.5,-5.5) AB28(11.5,-5.5) AB29(12.5,-5.5) AB30(13.5,-5.5) AB31(14.5,-5.5) AB32(15.5,-5.5) AC1(-15.5,-6.5) AC2(-14.5,-6.5) AC3(-13.5,-6.5) AC4(-12.5,-6.5) AC5(-11.5,-6.5) AC6(-10.5,-6.5) AC7(-9.5,-6.5) AC8(-8.5,-6.5) AC25(8.5,-6.5) AC26(9.5,-6.5) AC27(10.5,-6.5) AC28(11.5,-6.5) AC29(12.5,-6.5) AC30(13.5,-6.5) AC31(14.5,-6.5) AC32(15.5,-6.5) AD1(-15.5,-7.5) AD2(-14.5,-7.5) AD3(-13.5,-7.5) AD4(-12.5,-7.5) AD5(-11.5,-7.5) AD6(-10.5,-7.5) AD7(-9.5,-7.5) AD8(-8.5,-7.5) AD25(8.5,-7.5) AD26(9.5,-7.5) AD27(10.5,-7.5) AD28(11.5,-7.5) AD29(12.5,-7.5) AD30(13.5,-7.5) AD31(14.5,-7.5) AD32(15.5,-7.5) AE1(-15.5,-8.5) AE2(-14.5,-8.5) AE3(-13.5,-8.5) AE4(-12.5,-8.5) AE5(-11.5,-8.5) AE6(-10.5,-8.5) AE7(-9.5,-8.5) AE8(-8.5,-8.5) AE25(8.5,-8.5) AE26(9.5,-8.5) AE27(10.5,-8.5) AE28(11.5,-8.5) AE29(12.5,-8.5) AE30(13.5,-8.5) AE31(14.5,-8.5) AE32(15.5,-8.5) AF1(-15.5,-9.5) AF2(-14.5,-9.5) AF3(-13.5,-9.5) AF4(-12.5,-9.5) AF5(-11.5,-9.5) AF6(-10.5,-9.5) AF7(-9.5,-9.5) AF8(-8.5,-9.5) AF9(-7.5,-9.5) AF10(-6.5,-9.5) AF11(-5.5,-9.5) AF12(-4.5,-9.5) AF13(-3.5,-9.5) AF14(-2.5,-9.5) AF15(-1.5,-9.5) AF16(-0.5,-9.5) AF17(0.5,-9.5) AF18(1.5,-9.5) AF19(2.5,-9.5) AF20(3.5,-9.5) AF21(4.5,-9.5) AF22(5.5,-9.5) AF23(6.5,-9.5) AF24(7.5,-9.5) AF25(8.5,-9.5) AF26(9.5,-9.5) AF27(10.5,-9.5) AF28(11.5,-9.5) AF29(12.5,-9.5) AF30(13.5,-9.5) AF31(14.5,-9.5) AF32(15.5,-9.5) AG1(-15.5,-10.5) AG2(-14.5,-10.5) AG3(-13.5,-10.5) AG4(-12.5,-10.5) AG5(-11.5,-10.5) AG6(-10.5,-10.5) AG7(-9.5,-10.5) AG8(-8.5,-10.5) AG9(-7.5,-10.5) AG10(-6.5,-10.5) AG11(-5.5,-10.5) AG12(-4.5,-10.5) AG13(-3.5,-10.5) AG14(-2.5,-10.5) AG15(-1.5,-10.5) AG16(-0.5,-10.5) AG17(0.5,-10.5) AG18(1.5,-10.5) AG19(2.5,-10.5) AG20(3.5,-10.5) AG21(4.5,-10.5) AG22(5.5,-10.5) AG23(6.5,-10.5) AG24(7.5,-10.5) AG25(8.5,-10.5) AG26(9.5,-10.5) AG27(10.5,-10.5) AG28(11.5,-10.5) AG29(12.5,-10.5) AG30(13.5,-10.5) AG31(14.5,-10.5) AG32(15.5,-10.5) AH1(-15.5,-11.5) AH2(-14.5,-11.5) AH3(-13.5,-11.5) AH4(-12.5,-11.5) AH5(-11.5,-11.5) AH6(-10.5,-11.5) AH7(-9.5,-11.5) AH8(-8.5,-11.5) AH9(-7.5,-11.5) AH10(-6.5,-11.5) AH11(-5.5,-11.5) AH12(-4.5,-11.5) AH13(-3.5,-11.5) AH14(-2.5,-11.5) AH15(-1.5,-11.5) AH16(-0.5,-11.5) AH17(0.5,-11.5) AH18(1.5,-11.5) AH19(2.5,-11.5) AH20(3.5,-11.5) AH21(4.5,-11.5) AH22(5.5,-11.5) AH23(6.5,-11.5) AH24(7.5,-11.5) AH25(8.5,-11.5) AH26(9.5,-11.5) AH27(10.5,-11.5) AH28(11.5,-11.5) AH29(12.5,-11.5) AH30(13.5,-11.5) AH31(14.5,-11.5) AH32(15.5,-11.5) AJ1(-15.5,-12.5) AJ2(-14.5,-12.5) AJ3(-13.5,-12.5) AJ4(-12.5,-12.5) AJ5(-11.5,-12.5) AJ6(-10.5,-12.5) AJ7(-9.5,-12.5) AJ8(-8.5,-12.5) AJ9(-7.5,-12.5) AJ10(-6.5,-12.5) AJ11(-5.5,-12.5) AJ12(-4.5,-12.5) AJ13(-3.5,-12.5) AJ14(-2.5,-12.5) AJ15(-1.5,-12.5) AJ16(-0.5,-12.5) AJ17(0.5,-12.5) AJ18(1.5,-12.5) AJ19(2.5,-12.5) AJ20(3.5,-12.5) AJ21(4.5,-12.5) AJ22(5.5,-12.5) AJ23(6.5,-12.5) AJ24(7.5,-12.5) AJ25(8.5,-12.5) AJ26(9.5,-12.5) AJ27(10.5,-12.5) AJ28(11.5,-12.5) AJ29(12.5,-12.5) AJ30(13.5,-12.5) AJ31(14.5,-12.5) AJ32(15.5,-12.5) AK1(-15.5,-13.5) AK2(-14.5,-13.5) AK3(-13.5,-13.5) AK4(-12.5,-13.5) AK5(-11.5,-13.5) AK6(-10.5,-13.5) AK7(-9.5,-13.5) AK8(-8.5,-13.5) AK9(-7.5,-13.5) AK10(-6.5,-13.5) AK11(-5.5,-13.5) AK12(-4.5,-13.5) AK13(-3.5,-13.5) AK14(-2.5,-13.5) AK15(-1.5,-13.5) AK16(-0.5,-13.5) AK17(0.5,-13.5) AK18(1.5,-13.5) AK19(2.5,-13.5) AK20(3.5,-13.5) AK21(4.5,-13.5) AK22(5.5,-13.5) AK23(6.5,-13.5) AK24(7.5,-13.5) AK25(8.5,-13.5) AK26(9.5,-13.5) AK27(10.5,-13.5) AK28(11.5,-13.5) AK29(12.5,-13.5) AK30(13.5,-13.5) AK31(14.5,-13.5) AK32(15.5,-13.5) AL1(-15.5,-14.5) AL2(-14.5,-14.5) AL3(-13.5,-14.5) AL4(-12.5,-14.5) AL5(-11.5,-14.5) AL6(-10.5,-14.5) AL7(-9.5,-14.5) AL8(-8.5,-14.5) AL9(-7.5,-14.5) AL10(-6.5,-14.5) AL11(-5.5,-14.5) AL12(-4.5,-14.5) AL13(-3.5,-14.5) AL14(-2.5,-14.5) AL15(-1.5,-14.5) AL16(-0.5,-14.5) AL17(0.5,-14.5) AL18(1.5,-14.5) AL19(2.5,-14.5) AL20(3.5,-14.5) AL21(4.5,-14.5) AL22(5.5,-14.5) AL23(6.5,-14.5) AL24(7.5,-14.5) AL25(8.5,-14.5) AL26(9.5,-14.5) AL27(10.5,-14.5) AL28(11.5,-14.5) AL29(12.5,-14.5) AL30(13.5,-14.5) AL31(14.5,-14.5) AL32(15.5,-14.5) AM1(-15.5,-15.5) AM2(-14.5,-15.5) AM3(-13.5,-15.5) AM4(-12.5,-15.5) AM5(-11.5,-15.5) AM6(-10.5,-15.5) AM7(-9.5,-15.5) AM8(-8.5,-15.5) AM9(-7.5,-15.5) AM10(-6.5,-15.5) AM11(-5.5,-15.5) AM12(-4.5,-15.5) AM13(-3.5,-15.5) AM14(-2.5,-15.5) AM15(-1.5,-15.5) AM16(-0.5,-15.5) AM17(0.5,-15.5) AM18(1.5,-15.5) AM19(2.5,-15.5) AM20(3.5,-15.5) AM21(4.5,-15.5) AM22(5.5,-15.5) AM23(6.5,-15.5) AM24(7.5,-15.5) AM25(8.5,-15.5) AM26(9.5,-15.5) AM27(10.5,-15.5) AM28(11.5,-15.5) AM29(12.5,-15.5) AM30(13.5,-15.5) AM31(14.5,-15.5) AM32(15.5,-15.5) B1(-15.5,14.5) B2(-14.5,14.5) B3(-13.5,14.5) B4(-12.5,14.5) B5(-11.5,14.5) B6(-10.5,14.5) B7(-9.5,14.5) B8(-8.5,14.5) B9(-7.5,14.5) B10(-6.5,14.5) B11(-5.5,14.5) B12(-4.5,14.5) B13(-3.5,14.5) B14(-2.5,14.5) B15(-1.5,14.5) B16(-0.5,14.5) B17(0.5,14.5) B18(1.5,14.5) B19(2.5,14.5) B20(3.5,14.5) B21(4.5,14.5) B22(5.5,14.5) B23(6.5,14.5) B24(7.5,14.5) B25(8.5,14.5) B26(9.5,14.5) B27(10.5,14.5) B28(11.5,14.5) B29(12.5,14.5) B30(13.5,14.5) B31(14.5,14.5) B32(15.5,14.5) C1(-15.5,13.5) C2(-14.5,13.5) C3(-13.5,13.5) C4(-12.5,13.5) C5(-11.5,13.5) C6(-10.5,13.5) C7(-9.5,13.5) C8(-8.5,13.5) C9(-7.5,13.5) C10(-6.5,13.5) C11(-5.5,13.5) C12(-4.5,13.5) C13(-3.5,13.5) C14(-2.5,13.5) C15(-1.5,13.5) C16(-0.5,13.5) C17(0.5,13.5) C18(1.5,13.5) C19(2.5,13.5) C20(3.5,13.5) C21(4.5,13.5) C22(5.5,13.5) C23(6.5,13.5) C24(7.5,13.5) C25(8.5,13.5) C26(9.5,13.5) C27(10.5,13.5) C28(11.5,13.5) C29(12.5,13.5) C30(13.5,13.5) C31(14.5,13.5) C32(15.5,13.5) D1(-15.5,12.5) D2(-14.5,12.5) D3(-13.5,12.5) D4(-12.5,12.5) D5(-11.5,12.5) D6(-10.5,12.5) D7(-9.5,12.5) D8(-8.5,12.5) D9(-7.5,12.5) D10(-6.5,12.5) D11(-5.5,12.5) D12(-4.5,12.5) D13(-3.5,12.5) D14(-2.5,12.5) D15(-1.5,12.5) D16(-0.5,12.5) D17(0.5,12.5) D18(1.5,12.5) D19(2.5,12.5) D20(3.5,12.5) D21(4.5,12.5) D22(5.5,12.5) D23(6.5,12.5) D24(7.5,12.5) D25(8.5,12.5) D26(9.5,12.5) D27(10.5,12.5) D28(11.5,12.5) D29(12.5,12.5) D30(13.5,12.5) D31(14.5,12.5) D32(15.5,12.5) E1(-15.5,11.5) E2(-14.5,11.5) E3(-13.5,11.5) E4(-12.5,11.5) E5(-11.5,11.5) E6(-10.5,11.5) E7(-9.5,11.5) E8(-8.5,11.5) E9(-7.5,11.5) E10(-6.5,11.5) E11(-5.5,11.5) E12(-4.5,11.5) E13(-3.5,11.5) E14(-2.5,11.5) E15(-1.5,11.5) E16(-0.5,11.5) E17(0.5,11.5) E18(1.5,11.5) E19(2.5,11.5) E20(3.5,11.5) E21(4.5,11.5) E22(5.5,11.5) E23(6.5,11.5) E24(7.5,11.5) E25(8.5,11.5) E26(9.5,11.5) E27(10.5,11.5) E28(11.5,11.5) E29(12.5,11.5) E30(13.5,11.5) E31(14.5,11.5) E32(15.5,11.5) F1(-15.5,10.5) F2(-14.5,10.5) F3(-13.5,10.5) F4(-12.5,10.5) F5(-11.5,10.5) F6(-10.5,10.5) F7(-9.5,10.5) F8(-8.5,10.5) F9(-7.5,10.5) F10(-6.5,10.5) F11(-5.5,10.5) F12(-4.5,10.5) F13(-3.5,10.5) F14(-2.5,10.5) F15(-1.5,10.5) F16(-0.5,10.5) F17(0.5,10.5) F18(1.5,10.5) F19(2.5,10.5) F20(3.5,10.5) F21(4.5,10.5) F22(5.5,10.5) F23(6.5,10.5) F24(7.5,10.5) F25(8.5,10.5) F26(9.5,10.5) F27(10.5,10.5) F28(11.5,10.5) F29(12.5,10.5) F30(13.5,10.5) F31(14.5,10.5) F32(15.5,10.5) G1(-15.5,9.5) G2(-14.5,9.5) G3(-13.5,9.5) G4(-12.5,9.5) G5(-11.5,9.5) G6(-10.5,9.5) G7(-9.5,9.5) G8(-8.5,9.5) G9(-7.5,9.5) G10(-6.5,9.5) G11(-5.5,9.5) G12(-4.5,9.5) G13(-3.5,9.5) G14(-2.5,9.5) G15(-1.5,9.5) G16(-0.5,9.5) G17(0.5,9.5) G18(1.5,9.5) G19(2.5,9.5) G20(3.5,9.5) G21(4.5,9.5) G22(5.5,9.5) G23(6.5,9.5) G24(7.5,9.5) G25(8.5,9.5) G26(9.5,9.5) G27(10.5,9.5) G28(11.5,9.5) G29(12.5,9.5) G30(13.5,9.5) G31(14.5,9.5) G32(15.5,9.5) H1(-15.5,8.5) H2(-14.5,8.5) H3(-13.5,8.5) H4(-12.5,8.5) H5(-11.5,8.5) H6(-10.5,8.5) H7(-9.5,8.5) H8(-8.5,8.5) H9(-7.5,8.5) H10(-6.5,8.5) H11(-5.5,8.5) H12(-4.5,8.5) H13(-3.5,8.5) H14(-2.5,8.5) H15(-1.5,8.5) H16(-0.5,8.5) H17(0.5,8.5) H18(1.5,8.5) H19(2.5,8.5) H20(3.5,8.5) H21(4.5,8.5) H22(5.5,8.5) H23(6.5,8.5) H24(7.5,8.5) H25(8.5,8.5) H26(9.5,8.5) H27(10.5,8.5) H28(11.5,8.5) H29(12.5,8.5) H30(13.5,8.5) H31(14.5,8.5) H32(15.5,8.5) J1(-15.5,7.5) J2(-14.5,7.5) J3(-13.5,7.5) J4(-12.5,7.5) J5(-11.5,7.5) J6(-10.5,7.5) J7(-9.5,7.5) J8(-8.5,7.5) J25(8.5,7.5) J26(9.5,7.5) J27(10.5,7.5) J28(11.5,7.5) J29(12.5,7.5) J30(13.5,7.5) J31(14.5,7.5) J32(15.5,7.5) K1(-15.5,6.5) K2(-14.5,6.5) K3(-13.5,6.5) K4(-12.5,6.5) K5(-11.5,6.5) K6(-10.5,6.5) K7(-9.5,6.5) K8(-8.5,6.5) K25(8.5,6.5) K26(9.5,6.5) K27(10.5,6.5) K28(11.5,6.5) K29(12.5,6.5) K30(13.5,6.5) K31(14.5,6.5) K32(15.5,6.5) L1(-15.5,5.5) L2(-14.5,5.5) L3(-13.5,5.5) L4(-12.5,5.5) L5(-11.5,5.5) L6(-10.5,5.5) L7(-9.5,5.5) L8(-8.5,5.5) L25(8.5,5.5) L26(9.5,5.5) L27(10.5,5.5) L28(11.5,5.5) L29(12.5,5.5) L30(13.5,5.5) L31(14.5,5.5) L32(15.5,5.5) M1(-15.5,4.5) M2(-14.5,4.5) M3(-13.5,4.5) M4(-12.5,4.5) M5(-11.5,4.5) M6(-10.5,4.5) M7(-9.5,4.5) M8(-8.5,4.5) M14(-2.5,4.5) M20(3.5,4.5) M25(8.5,4.5) M26(9.5,4.5) M27(10.5,4.5) M28(11.5,4.5) M29(12.5,4.5) M30(13.5,4.5) M31(14.5,4.5) M32(15.5,4.5) N1(-15.5,3.5) N2(-14.5,3.5) N3(-13.5,3.5) N4(-12.5,3.5) N5(-11.5,3.5) N6(-10.5,3.5) N7(-9.5,3.5) N8(-8.5,3.5) N14(-2.5,3.5) N20(3.5,3.5) N25(8.5,3.5) N26(9.5,3.5) N27(10.5,3.5) N28(11.5,3.5) N29(12.5,3.5) N30(13.5,3.5) N31(14.5,3.5) N32(15.5,3.5) P1(-15.5,2.5) P2(-14.5,2.5) P3(-13.5,2.5) P4(-12.5,2.5) P5(-11.5,2.5) P6(-10.5,2.5) P7(-9.5,2.5) P8(-8.5,2.5) P14(-2.5,2.5) P20(3.5,2.5) P25(8.5,2.5) P26(9.5,2.5) P27(10.5,2.5) P28(11.5,2.5) P29(12.5,2.5) P30(13.5,2.5) P31(14.5,2.5) P32(15.5,2.5) R1(-15.5,1.5) R2(-14.5,1.5) R3(-13.5,1.5) R4(-12.5,1.5) R5(-11.5,1.5) R6(-10.5,1.5) R7(-9.5,1.5) R8(-8.5,1.5) R14(-2.5,1.5) R20(3.5,1.5) R25(8.5,1.5) R26(9.5,1.5) R27(10.5,1.5) R28(11.5,1.5) R29(12.5,1.5) R30(13.5,1.5) R31(14.5,1.5) R32(15.5,1.5) T1(-15.5,0.5) T2(-14.5,0.5) T3(-13.5,0.5) T4(-12.5,0.5) T5(-11.5,0.5) T6(-10.5,0.5) T7(-9.5,0.5) T8(-8.5,0.5) T14(-2.5,0.5) T20(3.5,0.5) T25(8.5,0.5) T26(9.5,0.5) T27(10.5,0.5) T28(11.5,0.5) T29(12.5,0.5) T30(13.5,0.5) T31(14.5,0.5) T32(15.5,0.5) U1(-15.5,-0.5) U2(-14.5,-0.5) U3(-13.5,-0.5) U4(-12.5,-0.5) U5(-11.5,-0.5) U6(-10.5,-0.5) U7(-9.5,-0.5) U8(-8.5,-0.5) U14(-2.5,-0.5) U20(3.5,-0.5) U25(8.5,-0.5) U26(9.5,-0.5) U27(10.5,-0.5) U28(11.5,-0.5) U29(12.5,-0.5) U30(13.5,-0.5) U31(14.5,-0.5) U32(15.5,-0.5) V1(-15.5,-1.5) V2(-14.5,-1.5) V3(-13.5,-1.5) V4(-12.5,-1.5) V5(-11.5,-1.5) V6(-10.5,-1.5) V7(-9.5,-1.5) V8(-8.5,-1.5) V14(-2.5,-1.5) V20(3.5,-1.5) V25(8.5,-1.5) V26(9.5,-1.5) V27(10.5,-1.5) V28(11.5,-1.5) V29(12.5,-1.5) V30(13.5,-1.5) V31(14.5,-1.5) V32(15.5,-1.5) W1(-15.5,-2.5) W2(-14.5,-2.5) W3(-13.5,-2.5) W4(-12.5,-2.5) W5(-11.5,-2.5) W6(-10.5,-2.5) W7(-9.5,-2.5) W8(-8.5,-2.5) W14(-2.5,-2.5) W20(3.5,-2.5) W25(8.5,-2.5) W26(9.5,-2.5) W27(10.5,-2.5) W28(11.5,-2.5) W29(12.5,-2.5) W30(13.5,-2.5) W31(14.5,-2.5) W32(15.5,-2.5) Y1(-15.5,-3.5) Y2(-14.5,-3.5) Y3(-13.5,-3.5) Y4(-12.5,-3.5) Y5(-11.5,-3.5) Y6(-10.5,-3.5) Y7(-9.5,-3.5) Y8(-8.5,-3.5) Y14(-2.5,-3.5) Y20(3.5,-3.5) Y25(8.5,-3.5) Y26(9.5,-3.5) Y27(10.5,-3.5) Y28(11.5,-3.5) Y29(12.5,-3.5) Y30(13.5,-3.5) Y31(14.5,-3.5) Y32(15.5,-3.5)
Top Overlay:
  circle w0.25: c-18.15,15.5 r0.125
  region: -16.5,17.5 -17.5,16.5 -17.5,17.5
  lines w0.2: -17.5,16.5 -16.5,17.5 ; -17.5,-17.5 17.5,-17.5 17.5,17.5 -17.5,17.5 -17.5,-17.5
Mechanical 13:
  lines w0.1: -17.5,-17.5 17.5,-17.5 17.5,17.5 -17.5,17.5 -17.5,-17.5
Mechanical 15:
  lines w0.1: -0.5,0 0.5,0 ; 0,-0.5 0,0.5 ; -18.5,-18.5 18.5,-18.5 18.5,18.5 -18.5,18.5 -18.5,-18.5
3D body: height 0, standoff 0, extent -17.5,-17.5 17.5,17.5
